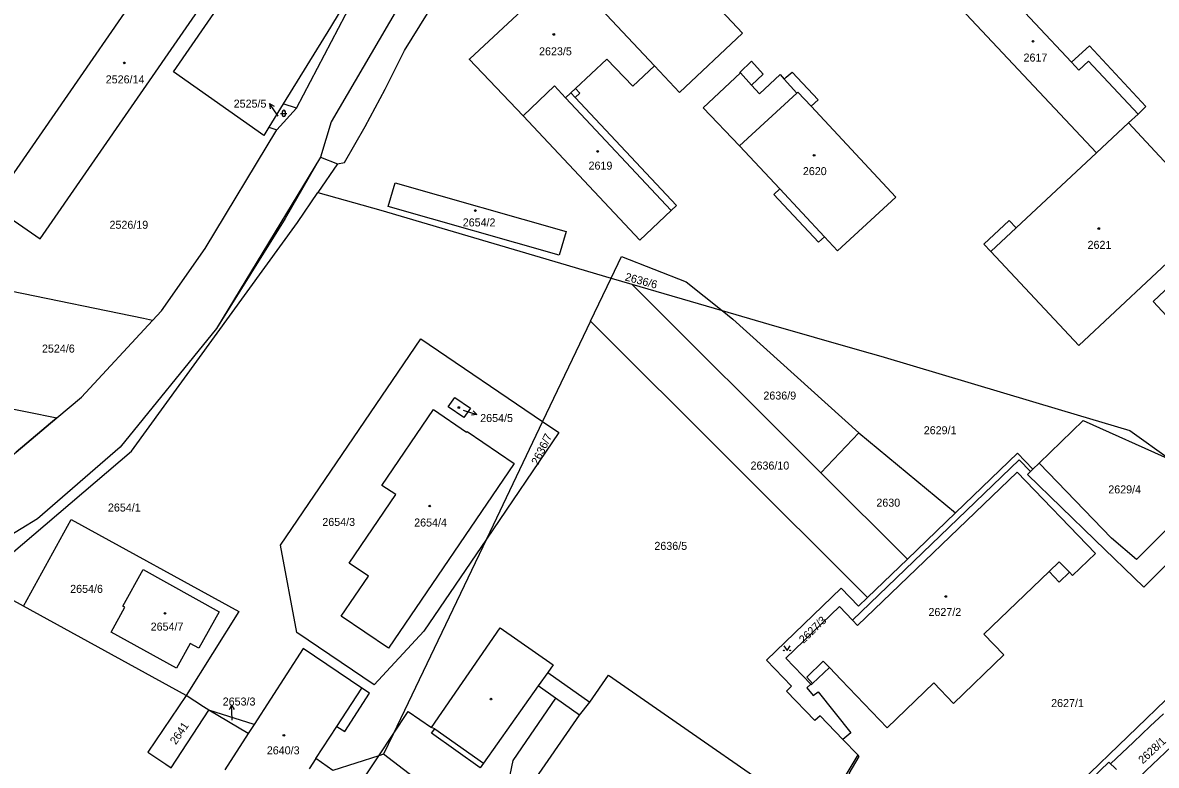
# Model space of a CAD drawing. Extents: x -527335 to -526256, y -1079142 to -1077809.
# Drawn here: x -527132.2 to -526891.4, y -1078599.7 to -1078442 of the extents above; entities that cross this region are included whole.
import ezdxf

# ---------------------------------------------------------------- set-up
doc = ezdxf.new("R2010")
doc.units = 0
for name, color, linetype in [('Vrstva 1', 7, 'Continuous'), ('Vrstva 2', 7, 'Continuous'), ('Vrstva 3', 7, 'Continuous'), ('Vrstva 4', 7, 'Continuous'), ('Vrstva 5', 7, 'Continuous'), ('Vrstva 54', 7, 'Continuous'), ('Vrstva 7', 7, 'Continuous')]:
    doc.layers.add(name, color=color, linetype=linetype)

msp = doc.modelspace()

# ---------------------------------------------------------------- linework, layer by layer
at = {"layer": 'Vrstva 1'}
for p, q in [((-527017.02, -1078430.86), (-526997.96, -1078451.19)), ((-526904.09, -1078469.66), (-526939.37, -1078432.13)), ((-527076.81, -1078459.26), (-527079.86, -1078464.22)), ((-527078.2, -1078464.76), (-527073.97, -1078460.17)), ((-527073.97, -1078460.17), (-527076.81, -1078459.26)), ((-527079.86, -1078464.22), (-527078.2, -1078464.76)), ((-526904.09, -1078469.66), (-526897.29, -1078463.32)), ((-527011.57, -1078505.42), (-527007.19, -1078496.25)), ((-527007.19, -1078496.25), (-527002.76, -1078497.55)), ((-527002.76, -1078497.55), (-526962.63, -1078537.57)), ((-527002.76, -1078497.55), (-526983.64, -1078503.15)), ((-527011.57, -1078505.42), (-527021.74, -1078526.69)), ((-526952.75, -1078564.07), (-527011.57, -1078505.42)), ((-527174.49, -1078515.96), (-527124.9, -1078525.93)), ((-526911.53, -1078524.31), (-526897.02, -1078528.64)), ((-527124.9, -1078525.93), (-527133.51, -1078533.2)), ((-527021.74, -1078526.69), (-527033.68, -1078551.66)), ((-526916.27, -1078535.54), (-526906.93, -1078526.46)), ((-526906.93, -1078526.46), (-526888.33, -1078534.82)), ((-526954.62, -1078529.11), (-526962.63, -1078537.57)), ((-526954.62, -1078529.11), (-526934.06, -1078546.1)), ((-526897.02, -1078528.64), (-526888.33, -1078534.82)), ((-526962.63, -1078537.57), (-526944.26, -1078555.9)), ((-526917.63, -1078536.86), (-526918.14, -1078537.35)), ((-526917.63, -1078536.86), (-526916.27, -1078535.54)), ((-526944.26, -1078555.9), (-526934.06, -1078546.1)), ((-526944.26, -1078555.9), (-526952.75, -1078564.07)), ((-527097.46, -1078584.88), (-527131.94, -1078565.93)), ((-527084.24, -1078592.92), (-527092.63, -1078588.02)), ((-527083.02, -1078591.02), (-527092.63, -1078588.02)), ((-527084.24, -1078592.92), (-527089.24, -1078600.63)), ((-527083.02, -1078591.02), (-527084.24, -1078592.92)), ((-526954.82, -1078597.51), (-526957.96, -1078594.24)), ((-527069.88, -1078598.28), (-527071.3, -1078600.46))]:
    msp.add_line(p, q, dxfattribs=at)
for points in [[(-526758.4, -1078472.62), (-526766.27, -1078446.58), (-526780.95, -1078423.56), (-526794.44, -1078407.43), (-526800.43, -1078400.96), (-526814.56, -1078388.75), (-526829.06, -1078378.91), (-526860.51, -1078363.6), (-526886.41, -1078357.78), (-526924.51, -1078355.89), (-526949.93, -1078359.99), (-526973.92, -1078367.12), (-526999.06, -1078381.03), (-527019.7, -1078396.51), (-527044.07, -1078424.46), (-527066.65, -1078463.1), (-527068.91, -1078470.58)], [(-527073.97, -1078460.17), (-527053.17, -1078420.48), (-527032.18, -1078397.77), (-527014.31, -1078382.24)], [(-527092.4, -1078413.63), (-527138.83, -1078480.75), (-527128.47, -1078487.92), (-527076.74, -1078413.16)], [(-527079.86, -1078464.22), (-527080.96, -1078466.02), (-527100.14, -1078452.45), (-527074.28, -1078415.06)], [(-527017.02, -1078430.86), (-527003.64, -1078418.3), (-527000.89, -1078421.23), (-526999.14, -1078419.57), (-526996.24, -1078422.65), (-526998, -1078424.3), (-526990.24, -1078432.57), (-526988.5, -1078431.05), (-526985.62, -1078434.17), (-526987.27, -1078435.73), (-526979.26, -1078444.26), (-526992.65, -1078456.85), (-526997.96, -1078451.19)], [(-526932.6, -1078425.71), (-526909.39, -1078450.45), (-526905.62, -1078446.98), (-526893.64, -1078459.85), (-526895.29, -1078461.46), (-526897.29, -1078463.32)], [(-527057.14, -1078427.02), (-527066.8, -1078442.97), (-527076.81, -1078459.26)], [(-527025.9, -1078461.78), (-527037.31, -1078449.81), (-527037.19, -1078449.7), (-527017.02, -1078430.86)], [(-526997.96, -1078451.19), (-527002.6, -1078455.49), (-527008.08, -1078449.75), (-527014.76, -1078456.01)], [(-526972.61, -1078478.49), (-526971.37, -1078477.33), (-526979.91, -1078468.16), (-526987.61, -1078460.08), (-526979.72, -1078452.7), (-526979.88, -1078452.59), (-526977.4, -1078450.22), (-526974.9, -1078452.93), (-526977.38, -1078455.27), (-526975.66, -1078457.15), (-526971.3, -1078453.02), (-526970.43, -1078453.99), (-526970.01, -1078453.63), (-526968.74, -1078452.52), (-526963.23, -1078458.42), (-526964.7, -1078459.79), (-526946.74, -1078479.09), (-526959.15, -1078490.45), (-526961.9, -1078487.49), (-526963.15, -1078488.65), (-526972.61, -1078478.49)], [(-527014.76, -1078456.01), (-527015.76, -1078456.95), (-527016.87, -1078458), (-527019.24, -1078455.47), (-527025.9, -1078461.78)], [(-527014.76, -1078456.01), (-527013.85, -1078456.97), (-527014.85, -1078457.92), (-526993.32, -1078480.86), (-526994.43, -1078481.91), (-527001.07, -1078488.2), (-527025.9, -1078461.78)], [(-527104.6, -1078505.26), (-527102.68, -1078503.19), (-527093.38, -1078489.99), (-527078.2, -1078464.76)], [(-526897.29, -1078463.32), (-526870.09, -1078492.57), (-526864.29, -1078487.18), (-526864.11, -1078487.39), (-526860.13, -1078491.78), (-526850.96, -1078483.22), (-526849.35, -1078484.86)], [(-526871.89, -1078509.77), (-526876.76, -1078504.18), (-526882.89, -1078509.7), (-526883.6, -1078510.36), (-526892.11, -1078501.21), (-526882.07, -1078491.81), (-526884.74, -1078488.89), (-526907.87, -1078510.54), (-526926.56, -1078490.64), (-526928.05, -1078489.06), (-526922.69, -1078484.05), (-526921.17, -1078485.61), (-526904.09, -1078469.66)], [(-527068.91, -1078470.58), (-527076.43, -1078483.63), (-527090.99, -1078506.94), (-527111.43, -1078532.12), (-527128.98, -1078547.4), (-527146.41, -1078557.97)], [(-527068.91, -1078470.58), (-527065.26, -1078472.03), (-527069.44, -1078478.09), (-527056.08, -1078481.87), (-527017.96, -1078493.09), (-527007.19, -1078496.25)], [(-527016.72, -1078486.4), (-527018.2, -1078491.42), (-527054.51, -1078481.04), (-527053.07, -1078476.01), (-527016.72, -1078486.4)], [(-527007.19, -1078496.25), (-527005, -1078491.67), (-526991.23, -1078497.03), (-526983.64, -1078503.15)], [(-527104.6, -1078505.26), (-527106.49, -1078504.87), (-527163.05, -1078493.2), (-527166.58, -1078492.47)], [(-526983.64, -1078503.15), (-526973.71, -1078506.06), (-526954.42, -1078511.53), (-526949.93, -1078512.86), (-526911.53, -1078524.31)], [(-526983.64, -1078503.15), (-526981.37, -1078504.98), (-526954.62, -1078529.11)], [(-527124.9, -1078525.93), (-527119.69, -1078521.54), (-527104.6, -1078505.26)], [(-527033.68, -1078551.66), (-527046.99, -1078571.23), (-527057.48, -1078582.63), (-527073.96, -1078571.48), (-527077.41, -1078552.98), (-527047.57, -1078509.12), (-527021.74, -1078526.69)], [(-527038.48, -1078525.83), (-527041.78, -1078523.58), (-527040.37, -1078521.59), (-527037.07, -1078523.84), (-527038.48, -1078525.83)], [(-527054.44, -1078574.86), (-527064.51, -1078568.02), (-527058.74, -1078559.53), (-527062.84, -1078556.76), (-527052.94, -1078542.2), (-527055.85, -1078540.27), (-527044.91, -1078524.13), (-527037.87, -1078528.95), (-527037.79, -1078528.84), (-527027.75, -1078535.64), (-527054.44, -1078574.86)], [(-527021.74, -1078526.69), (-527018.3, -1078529.03), (-527033.68, -1078551.66)], [(-526918.14, -1078537.35), (-526920.53, -1078534.86), (-526955.95, -1078568.9)], [(-526934.06, -1078546.1), (-526920.91, -1078533.44), (-526917.63, -1078536.86)], [(-526955.95, -1078568.9), (-526954.86, -1078570.05), (-526920.93, -1078537.44), (-526904.33, -1078554.71), (-526909.19, -1078559.38), (-526909.87, -1078558.68), (-526912.06, -1078560.79), (-526914.19, -1078558.58), (-526928.01, -1078571.89), (-526923.77, -1078576.27), (-526934.47, -1078586.55), (-526938.68, -1078582.18), (-526948.58, -1078591.71), (-526958.37, -1078581.52), (-526960.85, -1078578.95), (-526964.39, -1078582.3), (-526964.69, -1078582.6), (-526964.8, -1078582.49)], [(-526918.14, -1078537.35), (-526918.76, -1078537.96), (-526904.45, -1078551.8), (-526894.03, -1078561.87), (-526887.38, -1078555.19), (-526885.32, -1078553.06), (-526881, -1078548.61), (-526877.52, -1078545.02), (-526875.12, -1078541.14)], [(-526878.8, -1078539.1), (-526895.62, -1078555.97), (-526900.9, -1078551.5), (-526916.27, -1078535.54)], [(-527131.94, -1078565.93), (-527121.85, -1078547.54), (-527086.27, -1078567.07), (-527097.46, -1078584.88)], [(-527033.68, -1078551.66), (-527053.5, -1078593.1), (-527055.53, -1078597.34)], [(-527131.94, -1078565.93), (-527141.5, -1078560.67), (-527146.41, -1078557.97)], [(-527106.58, -1078558.1), (-527090.44, -1078567.11), (-527094.71, -1078574.84), (-527096.57, -1078573.81), (-527099.47, -1078579.07), (-527113.37, -1078571.46), (-527110.45, -1078566.13), (-527110.89, -1078565.89), (-527106.58, -1078558.1)], [(-526957.96, -1078594.24), (-526962.83, -1078589.17), (-526963.91, -1078590.21), (-526969.95, -1078583.94), (-526968.87, -1078582.9), (-526974.21, -1078577.35), (-526958.32, -1078562.06), (-526954.64, -1078565.89), (-526952.75, -1078564.07)], [(-526955.95, -1078568.9), (-526958.71, -1078566), (-526970.06, -1078576.93), (-526964.8, -1078582.49)], [(-527032.9, -1078614.69), (-527028.96, -1078608.95), (-527028.74, -1078608.62), (-527027.84, -1078609.21), (-527013.93, -1078589.06), (-527018.97, -1078585.47), (-527022.71, -1078582.8), (-527034.32, -1078599.25), (-527035, -1078600.21), (-527045.31, -1078592.89), (-527044.64, -1078591.95), (-527045.34, -1078591.68), (-527030.72, -1078570.54), (-527019.5, -1078578.37), (-527020.66, -1078580.03), (-527011.71, -1078586.28), (-527007.77, -1078580.59), (-526958.39, -1078614.81), (-526968.02, -1078629.02)], [(-527069.88, -1078598.28), (-527065.44, -1078591.44), (-527063.76, -1078592.53), (-527058.48, -1078584.39), (-527060.16, -1078583.3), (-527072.6, -1078574.92), (-527083.02, -1078591.02)], [(-526964.8, -1078582.49), (-526965.63, -1078583.26), (-526964.25, -1078584.91), (-526963.24, -1078584.12), (-526956.3, -1078592.83), (-526957.96, -1078594.24)], [(-527097.46, -1078584.88), (-527105.59, -1078596.9), (-527101.78, -1078599.46), (-527100.62, -1078600.24), (-527092.63, -1078588.02)], [(-527092.63, -1078588.02), (-527093.75, -1078587.29), (-527097.46, -1078584.88)], [(-526886.71, -1078584.76), (-526887.47, -1078583.94), (-526927.4, -1078622.44), (-526930.86, -1078618.91), (-526934.27, -1078622.19), (-526943.73, -1078612.76), (-526944.56, -1078613.6), (-526956.67, -1078601.43), (-526954.52, -1078597.86), (-526954.82, -1078597.51)], [(-526889.91, -1078588.74), (-526892.73, -1078591.42), (-526896.25, -1078594.77), (-526901.11, -1078599.39)], [(-526895.17, -1078602.34), (-526893.54, -1078600.8), (-526885.48, -1078593.16)], [(-527055.53, -1078597.34), (-527056.53, -1078597.66), (-527066.26, -1078600.79), (-527069.88, -1078598.28)], [(-527032.9, -1078614.69), (-527038.13, -1078610.68), (-527051.29, -1078600.6), (-527055.53, -1078597.34)], [(-526954.82, -1078597.51), (-526957.37, -1078601.73), (-526935.75, -1078624.2), (-526927.86, -1078624.35), (-526901.5, -1078599), (-526901.11, -1078599.39)], [(-526901.11, -1078599.39), (-526900.32, -1078600.17), (-526899.88, -1078600.6)]]:
    msp.add_lwpolyline(points, dxfattribs=at)
at = {"layer": 'Vrstva 3'}
for p, q in [((-527077.37, -1078461.3), (-527076.03, -1078461.3)), ((-527077.04, -1078460.97), (-527077.04, -1078461.64)), ((-527076.36, -1078461.64), (-527076.36, -1078460.97))]:
    msp.add_line(p, q, dxfattribs=at)
msp.add_lwpolyline([(-526970.51, -1078574.3), (-526969.84, -1078575.31), (-526969.17, -1078574.3)], dxfattribs=at)
for centre in [(-526970.51, -1078575.31), (-526969.17, -1078575.31)]:
    msp.add_circle(centre, 0.067, dxfattribs=at)
for centre, start, end in [((-527076.7, -1078460.97), 0, 180), ((-527076.7, -1078461.64), 180, 359.9879)]:
    msp.add_arc(centre, 0.335, start, end, dxfattribs=at)
at = {"layer": 'Vrstva 4'}
for p, q in [((-527051.06, -1078447.97), (-527046.19, -1078440.05)), ((-527055.18, -1078456.16), (-527051.06, -1078447.97)), ((-526909.39, -1078450.45), (-526907.86, -1078452.08)), ((-526907.86, -1078452.08), (-526905.84, -1078450.2)), ((-526905.84, -1078450.2), (-526895.29, -1078461.46)), ((-526977.38, -1078455.27), (-526979.72, -1078452.7)), ((-526967.74, -1078456.98), (-526970.43, -1078453.99)), ((-527059.42, -1078464.07), (-527055.18, -1078456.16)), ((-527016.87, -1078458), (-526994.43, -1078481.91)), ((-527014.85, -1078457.92), (-527015.76, -1078456.95)), ((-526979.91, -1078468.16), (-526967.74, -1078456.98)), ((-526967.74, -1078456.98), (-526967.51, -1078456.77)), ((-526967.51, -1078456.77), (-526964.7, -1078459.79)), ((-527063.81, -1078471.71), (-527059.42, -1078464.07)), ((-527065.26, -1078472.03), (-527063.81, -1078471.71)), ((-526971.37, -1078477.33), (-526961.9, -1078487.49)), ((-527073.82, -1078484.44), (-527069.44, -1078478.09)), ((-527109.01, -1078533.01), (-527073.82, -1078484.44)), ((-526926.56, -1078490.64), (-526921.17, -1078485.61)), ((-527141.5, -1078560.67), (-527109.01, -1078533.01)), ((-526914.19, -1078558.58), (-526912.01, -1078556.48)), ((-526912.01, -1078556.48), (-526909.87, -1078558.68)), ((-526965.63, -1078581), (-526962.13, -1078577.61)), ((-526962.13, -1078577.61), (-526960.85, -1078578.95)), ((-527020.66, -1078580.03), (-527022.71, -1078582.8)), ((-526964.39, -1078582.3), (-526965.63, -1078581)), ((-527065.44, -1078591.44), (-527060.16, -1078583.3)), ((-527018.97, -1078585.47), (-527028.09, -1078598.67)), ((-527013.93, -1078589.06), (-527011.71, -1078586.28)), ((-527053.5, -1078593.1), (-527050.3, -1078588.28)), ((-527050.3, -1078588.28), (-527045.34, -1078591.68)), ((-527044.64, -1078591.95), (-527034.32, -1078599.25)), ((-527056.53, -1078597.66), (-527053.5, -1078593.1)), ((-527061.99, -1078605.89), (-527056.53, -1078597.66)), ((-527028.09, -1078598.67), (-527030.01, -1078608.26))]:
    msp.add_line(p, q, dxfattribs=at)
at = {"layer": 'Vrstva 5'}
for centre in [(-527019.36, -1078444.53), (-526917.6, -1078445.98), (-527110.57, -1078450.57), (-527010.04, -1078469.38), (-526964.08, -1078470.21), (-527036.01, -1078481.92), (-526903.63, -1078485.74), (-527039.53, -1078523.74), (-527045.71, -1078544.65), (-526936.12, -1078563.86), (-527101.92, -1078567.45), (-527032.71, -1078585.65), (-527076.68, -1078593.34)]:
    msp.add_circle(centre, 0.175, dxfattribs=at)
at = {"layer": 'Vrstva 54'}
for points in [[(-527211.21, -1078569.97), (-527206.43, -1078566.42), (-527198.92, -1078564.35), (-527186.55, -1078560.94), (-527171.22, -1078554.58), (-527156.15, -1078546.29), (-527134.58, -1078534.1), (-527133.51, -1078533.2), (-527124.9, -1078525.93), (-527119.69, -1078521.54), (-527104.6, -1078505.26), (-527102.68, -1078503.19), (-527093.38, -1078489.99), (-527078.2, -1078464.76), (-527073.97, -1078460.17), (-527053.17, -1078420.48)], [(-527044.07, -1078424.46), (-527066.65, -1078463.1), (-527068.91, -1078470.58), (-527090.99, -1078506.94), (-527111.43, -1078532.12), (-527128.98, -1078547.4), (-527146.41, -1078557.97), (-527152.71, -1078561.79), (-527177.41, -1078571.47), (-527199.41, -1078575.6), (-527202.75, -1078576.23), (-527217.79, -1078579.29), (-527215.15, -1078575.44)]]:
    msp.add_lwpolyline(points, dxfattribs=at)
at = {"layer": 'Vrstva 7'}
for p, q in [((-527078.01, -1078461.68), (-527079.73, -1078459.22)), ((-527079.73, -1078459.22), (-527078.75, -1078459.76)), ((-527079.73, -1078459.22), (-527079.57, -1078460.33)), ((-527077.87, -1078461.87), (-527078.01, -1078461.68)), ((-527038.58, -1078524.33), (-527035.71, -1078525.21)), ((-527035.71, -1078525.21), (-527036.81, -1078525.39)), ((-527035.71, -1078525.21), (-527036.52, -1078524.44)), ((-527087.82, -1078586.9), (-527088.27, -1078587.93)), ((-527087.66, -1078589.9), (-527087.82, -1078586.9)), ((-527087.82, -1078586.9), (-527087.27, -1078587.88)), ((-527087.65, -1078590.15), (-527087.66, -1078589.9))]:
    msp.add_line(p, q, dxfattribs=at)

# ---------------------------------------------------------------- texts
at = {"layer": 'Vrstva 2'}
for s, p in [('2623/5', (-527022.49, -1078448.96)), ('2617', (-526919.61, -1078450.29)), ('2526/14', (-527114.51, -1078454.92)), ('2525/5', (-527087.34, -1078460.07)), ('2619', (-527011.98, -1078473.23)), ('2620', (-526966.47, -1078474.4)), ('2526/19', (-527113.71, -1078485.79)), ('2654/2', (-527038.7, -1078485.29)), ('2621', (-526906.01, -1078490.05)), ('2524/6', (-527128.05, -1078512.07)), ('2636/9', (-526974.85, -1078522.05)), ('2654/5', (-527034.99, -1078526.82)), ('2629/1', (-526940.8, -1078529.41)), ('2636/10', (-526977.58, -1078536.91)), ('2629/4', (-526901.61, -1078541.97)), ('2654/1', (-527114.04, -1078545.82)), ('2630', (-526950.86, -1078544.79)), ('2654/3', (-527068.52, -1078548.88)), ('2654/4', (-527049.01, -1078549)), ('2636/5', (-526998, -1078553.96)), ('2654/6', (-527122.06, -1078563.09)), ('2627/2', (-526939.8, -1078568)), ('2654/7', (-527104.97, -1078571.1)), ('2653/3', (-527089.67, -1078587.01)), ('2627/1', (-526913.75, -1078587.33)), ('2640/3', (-527080.3, -1078597.37))]:
    msp.add_text(s, height=1.7, dxfattribs=at).set_placement(p)
for s, rotation, p in [('2636/6', 345, (-527004.36, -1078496.73)), ('2636/7', 64, (-527022.71, -1078536.05)), ('2627/3', 44, (-526966.32, -1078573.94)), ('2641', 56, (-527099.61, -1078595.45)), ('2628/1', 43, (-526894.29, -1078599.51))]:
    msp.add_text(s, height=1.7, rotation=rotation, dxfattribs=at).set_placement(p)

doc.saveas('drawing.dxf')
